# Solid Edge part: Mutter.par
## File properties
Sűrűség: 0,000 kg/m^3
Pontosság: 0,990
Author: bmolnar
Last saved by: bmolnar
Revision: 76
Username: bmolnar
Dokumentum tartalom típus: 0
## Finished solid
Body 1: solid body, 23 faces, 46 edges, 24 vertices.
  Faces by surface: cone 14, plane 8, cylinder 1
  Edges by curve: spline 24, circle 16, line 6
Bounding box of the edges (mm): 5.000 x 15.011 x 13.000, from (0, -7.5056, -6.5) to (5, 7.5056, 6.5).
Cylindrical faces by radius (mm): R3.3235 x1
Conical faces (half-angle, radius in mm at the cone's reference point): 60 deg R3.6618 x2, 60 deg R7.0028 x12
Planar faces by outward normal: +x 1, +z 1, -x 1, -z 1, oblique 4
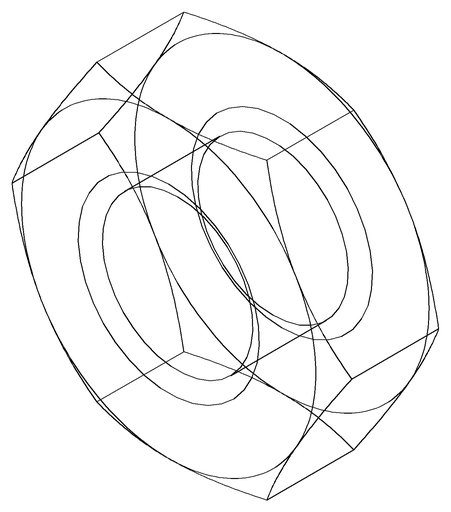
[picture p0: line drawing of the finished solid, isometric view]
